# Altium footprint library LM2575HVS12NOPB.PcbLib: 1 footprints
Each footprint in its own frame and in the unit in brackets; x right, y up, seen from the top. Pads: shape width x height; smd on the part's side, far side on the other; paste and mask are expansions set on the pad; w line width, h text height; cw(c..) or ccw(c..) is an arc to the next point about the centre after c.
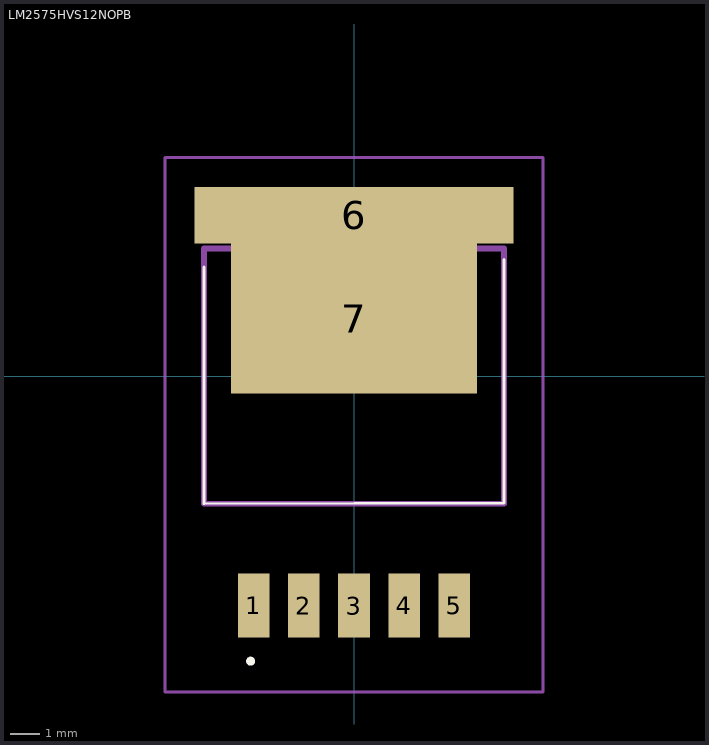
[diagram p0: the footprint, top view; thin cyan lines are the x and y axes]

## LM2575HVS12NOPB [mm]
pads (7):
  rect 1.07x2.16 smd: 1(-3.4,-7.769) 2(-1.7,-7.769) 3(0,-7.769) 4(1.7,-7.769) 5(3.4,-7.769)
  rect 10.8x1.91 smd: 6(0,5.446)
  rect 8.33x5.08 smd: 7(0,1.95)
Top Overlay:
  lines w0.1: -5.08,3.7 -5.08,-4.32 5.08,-4.3 5.08,3.95
  lines w0.2: -3.5,-9.7 cw(c-3.5,-9.65) -3.5,-9.6 ; -3.5,-9.7 -3.5,-9.7 ; -3.5,-9.7 ccw(c-3.5,-9.65) -3.5,-9.6 ; -3.5,-9.7 cw(c-3.5,-9.65) -3.5,-9.6 ; -3.5,-9.6 -3.5,-9.6 ; -3.5,-9.6 -3.5,-9.6
Mechanical 15:
  lines w0.2: -5.08,-4.32 5.08,-4.32 5.08,4.32 -5.08,4.32 -5.08,-4.32
Mechanical 20:
  lines w0.1: -6.4,-10.7 6.4,-10.7 6.4,7.401 -6.4,7.401 -6.4,-10.7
